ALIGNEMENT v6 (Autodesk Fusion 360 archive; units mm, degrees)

design "ALIGNEMENT" references "IUT GMP BESANCON 5AX130"
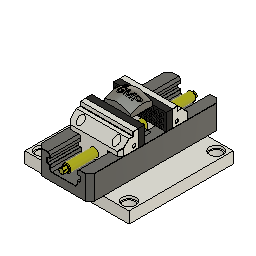
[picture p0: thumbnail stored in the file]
parameter "Ouverture" = 51
parameter "Ouverture_1" = 51
sketch "Esquisse1" plane through (0, 0, 0) normal (0, 0, 1) x axis (1, 0, 0)
  line L1 (-31, -25.5) -> (31, -25.5)
  line L2 (-31, 25.5) -> (-31, -25.5)
  line L3 (31, 25.5) -> (-31, 25.5)
  line L4 (31, -25.5) -> (31, 25.5)
  line L5 (-31, 25.5) -> (31, -25.5)
  line L6 (31, 25.5) -> (-31, -25.5)
  point P6 (0, 0)
  point P1 (0, 0)
  point P4 (-31, 25.5)
  point P5 (31, 25.5)
  point P3 (-31, -25.5)
  horizontal L1
  perpendicular L1 L2
  parallel L1 L3
  parallel L2 L4
  coincident L5 P6
  coincident L6 P6
  coincident P1 P6
  dimension "d1" distance P4 P5 = 62
  dimension "d2" distance P3 P4 = 51
extrude "Extrusion1" new body sketch "Esquisse1" profile of L1 L2 L3 L4 along normal blind 35
sketch "Esquisse2" plane through (0, -25.5, 0) normal (0, -1, 0) x axis (1, 0, 0)
  curve K1 (-1.414, 20.3628) -> (31, 8.565)
  line L1 (-31, 35) -> (-31, 0)
  line L2 (31, 35) -> (31, 0)
  point P2 (-31, 10.3414)
  point P3 (31, 8.565)
  coincident P2 L1
  coincident P3 L2
sketch "Esquisse3" plane through (-31, 0, 0) normal (-1, 0, 0) x axis (0, -1, 0)
  curve K1 (-2.9428, 20.0252) -> (-25.5, 13.369)
  line L1 (-25.5, 35) -> (-25.5, 0)
  point P3 (-25.5, 13.369)
  point P2 (25.5, 10.3414)
  point P5 (25.5, 10.3414)
  coincident P3 L1
  coincident P2 P5
sweep "Balayage"
split "Scinder"
remove_body "RemoveBody1"
work_plane "Plan de construction" AlongDistance 45
sketch "Esquisse4" plane through (0, 0, 45) normal (0, 0, 1) x axis (1, 0, 0)
  dimension "d14" = 17
emboss "Gravure en relief" sketch "Esquisse4" Depth -0.1 Horizontal Distance 0 Vertical Distance 0
sketch "Esquisse5" plane through (0, 0, 0) normal (0, 0, -1) x axis (1, 0, 0)
  line L1 (31, 25.5) -> (-31, -25.5)
  point P2 (-31, -25.5)
  point P3 (-31, -25.5)
  point P4 (31, 25.5)
  point P5 (31, 25.5)
  point P1 (0, 0)
  point P6 (0, 0)
  coincident P2 P3
  coincident P4 P5
  coincident P1 P6
sketch "Esquisse6" plane through (0, 0, 0) normal (0, 1, 0) x axis (1, 0, 0)
  curve K1 (31, -15.9892) -> (-31, -17.7656)
  curve K2 (22.4494, 7.5031) -> (-22.9795, 5.9129)
  dimension "d19" = -25
sketch "Esquisse7" plane through (0, 0, 45) normal (0, 0, 1) x axis (1, 0, 0)
  line L1 (-31, 25.5) -> (31, 25.5)
  line L2 (-31, -25.5) -> (-31, 25.5)
  circle C1 centre (-23, 17.5) radius 6
  point P2 (-23, 17.5)
  dimension "d20" diameter C1 = 12
  dimension "d21" distance P2 L1 = 8
  dimension "d22" distance P2 L2 = 8
extrude "Extrusion2" cut sketch "Esquisse7" profile of C1 against normal blind 38
base_feature "Base Feature1" OffsetX 0 named "d5_1" OffsetY 0 named "d6_1" OffsetZ 0 named "d7_1" OffsetX 0 named "d18_1" OffsetY 0 named "d19_1" OffsetZ 0 named "d20_1" OffsetX 0 OffsetY 0 OffsetZ 0 OffsetX 0 OffsetY 0 OffsetZ 0
base_feature "Base Feature1" OffsetX 0 named "d1_1" OffsetY 0 named "d2_1" OffsetZ 0 named "d3_1" OffsetX 0 named "d14_1" OffsetY 0 named "d15_1" OffsetZ 0 named "d16_1" OffsetX 0 OffsetY 0 OffsetZ 0 OffsetX 0 OffsetY 0 OffsetZ 0
work_plane "WorkPlane2"
base_feature "Base Feature1"
position "Position1"
sketch "Sketch1" plane through (9.1729, 31.8972, 315) normal (1, 0, 0) x axis (0, 1, 0)
work_axis "WorkAxis1"
work_point "WorkPoint1"
joint_origin "JointOrigin7" OffsetX 0 OffsetY 0 OffsetZ 0
work_point "WorkPoint2"
work_point "WorkPoint1"
position "Position2"
position "Position3"
joint_origin "JointOrigin8" OffsetX 0 OffsetY 0 OffsetZ 0
joint_origin "JointOrigin3" OffsetX 0 OffsetY 0 OffsetZ 0
position "Position4"
ground "Terre5"
position "Position5"
ground "Terre6"
joint "Assembler5" alignOffsetX 0 alignOffsetY 0 alignOffsetZ 0
joint "Assembler6" alignOffsetX 0 alignOffsetY 0 alignOffsetZ 0
position "Position6" TranslateAlongZ -25.5 (= "-Ouverture / 2") TranslateAlongZ 25.5 (= "Ouverture / 2")
as_built_joint "Réelle2"
ground "Libérer"
base_feature "Base Feature1"
base_feature "Base Feature1"
base_feature "Base Feature1"
position "Position1"
joint_origin "JointOrigin1" OffsetX 0 named "d1_2" OffsetY 0 named "d2_2" OffsetZ 0 named "d3_2"
joint_origin "JointOrigin2" OffsetX 0 named "d5_2" OffsetY 0 named "d6_2" OffsetZ 0 named "d7_2"
joint_origin "JointOrigin1" OffsetX 0 named "d9_1" OffsetY 0 named "d10_1" OffsetZ 0 named "d11_1"
joint "Assemble1" alignOffsetX 0 named "d14_2" alignOffsetY 0 named "d15_2" alignOffsetZ -2.8 (= "-Ouverture_1 / 2 + 22.7 mm") named "d16_2"
joint "Assemble2" alignOffsetX 0 named "d23_1" alignOffsetY 0 named "d24_1" alignOffsetZ 2.8 (= "Ouverture_1 / 2 - 22.7 mm")
as_built_joint "Réelle1"
as_built_joint "Réelle3"
position "Position1"
position "Position2"
work_axis "Axe de construction"
work_point "WorkPoint1"
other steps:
create_component "CreateComponent1"
create_component "CreateComponent1"
create_component "CreateComponent2"
create_component "CreateComponent2"
create_component "CreateComponent1"
create_component "CreateComponent1"
create_component "CreateComponent2"
create_component "CreateComponent3"
joint_origin "JointOrigin2" OffsetX 0 named "d18_2" OffsetY 0 named "d19_2" OffsetZ 0 named "d20_2"
create_component "CreateComponent2"

design "IUT GMP BESANCON 5AX130"
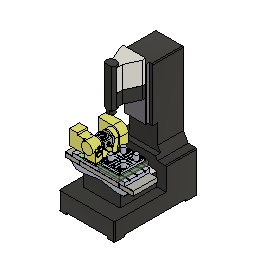
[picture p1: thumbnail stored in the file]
